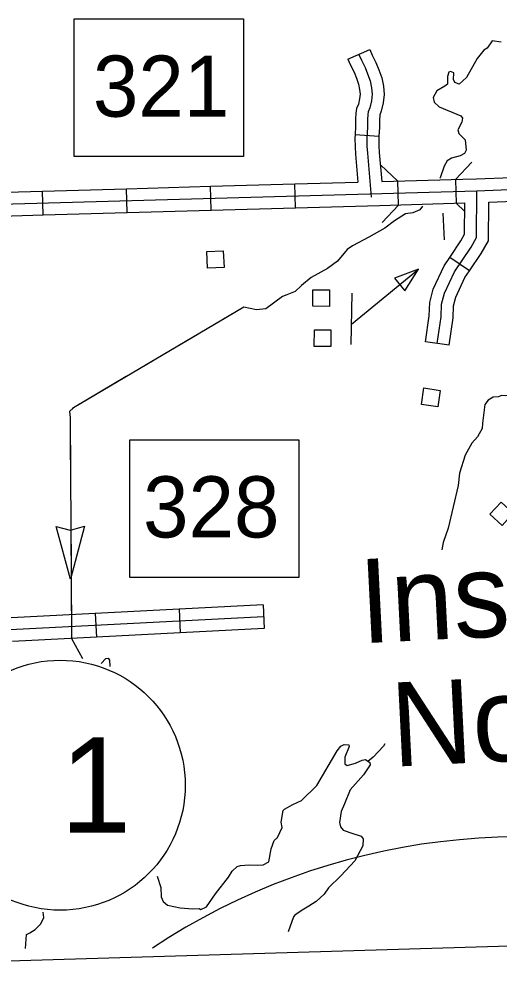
# Model space of a CAD drawing. Extents: x 1671357 to 13005564, y 567358 to 14261451.
# Drawn here: x 12758300.579 to 12758301.586, y 14259944.261 to 14259946.246 of the extents above; entities that cross this region are included whole.
import ezdxf

# ---------------------------------------------------------------- set-up
doc = ezdxf.new("R2010")
doc.units = 0
for name, color, linetype in [('32', 7, 'Continuous'), ('35', 7, 'Continuous'), ('38', 7, 'Continuous'), ('56', 7, 'Continuous'), ('63', 7, 'Continuous'), ('Default', 7, 'Continuous')]:
    doc.layers.add(name, color=color, linetype=linetype)

msp = doc.modelspace()

# ---------------------------------------------------------------- linework, layer by layer
at = {"layer": '32'}
for p, q in [((12758301.2694, 14259946.1615), (12758301.3151, 14259946.1818)), ((12758301.2842, 14259946.0033), (12758301.3341, 14259946.0002)), ((12758301.3753, 14259945.8559), (12758301.3739, 14259945.9059)), ((12758301.4968, 14259945.8589), (12758301.4954, 14259945.9089)), ((12758300.6304, 14259945.8347), (12758300.6289, 14259945.8847)), ((12758300.8066, 14259945.8397), (12758300.8051, 14259945.8897)), ((12758300.9828, 14259945.8447), (12758300.9813, 14259945.8948)), ((12758301.159, 14259945.8497), (12758301.1576, 14259945.8998)), ((12758301.5243, 14259945.7176), (12758301.4829, 14259945.7457)), ((12758301.4816, 14259945.5612), (12758301.432, 14259945.5682)), ((12758300.9151, 14259945.0077), (12758300.9177, 14259944.9577)), ((12758301.0912, 14259945.0168), (12758301.0937, 14259944.9668)), ((12758300.7391, 14259944.9987), (12758300.7417, 14259944.9487))]:
    msp.add_line(p, q, dxfattribs=at)
for points in [[(12758301.3151, 14259946.1818), (12758301.3203, 14259946.1701), (12758301.3281, 14259946.1545), (12758301.3341, 14259946.1395), (12758301.3401, 14259946.1224), (12758301.3436, 14259946.105), (12758301.345, 14259946.0877), (12758301.3434, 14259946.0703), (12758301.3391, 14259946.0522), (12758301.3362, 14259946.0449), (12758301.3359, 14259946.0431), (12758301.3354, 14259946.034), (12758301.3353, 14259946.0182), (12758301.3341, 14259946.0002)], [(12758301.2694, 14259946.1615), (12758301.275, 14259946.1488), (12758301.2824, 14259946.134), (12758301.2872, 14259946.1219), (12758301.2917, 14259946.1092), (12758301.2939, 14259946.098), (12758301.2947, 14259946.0879), (12758301.2939, 14259946.0784), (12758301.2912, 14259946.0674), (12758301.2874, 14259946.0578), (12758301.2861, 14259946.0481), (12758301.2853, 14259946.0357), (12758301.2852, 14259946.02), (12758301.2842, 14259946.0033)], [(12758301.2922, 14259946.1716), (12758301.2977, 14259946.1594), (12758301.3052, 14259946.1443), (12758301.3107, 14259946.1307), (12758301.3159, 14259946.1158), (12758301.3187, 14259946.1015), (12758301.3199, 14259946.0878), (12758301.3187, 14259946.0744), (12758301.3152, 14259946.0598), (12758301.3118, 14259946.0513), (12758301.311, 14259946.0456), (12758301.3104, 14259946.0349), (12758301.3102, 14259946.0191), (12758301.3087, 14259945.9953), (12758301.3093, 14259945.9789), (12758301.3102, 14259945.9641), (12758301.318, 14259945.8723)], [(12758300.2528, 14259946.014), (12758300.2662, 14259945.8494), (12758301.54, 14259945.8856), (12758301.8633, 14259945.8984), (12758301.8808, 14259945.9032), (12758301.8891, 14259945.9062), (12758301.8966, 14259945.9179), (12758301.9791, 14259946.0887), (12758301.9968, 14259946.1059), (12758302.0098, 14259946.1131), (12758302.0326, 14259946.1185), (12758302.0747, 14259946.1192), (12758302.3774, 14259946.1157), (12758302.3954, 14259946.1155), (12758302.4022, 14259946.1138), (12758302.4147, 14259946.0952)], [(12758301.2842, 14259946.0033), (12758301.2837, 14259945.9956), (12758301.2843, 14259945.9777), (12758301.2852, 14259945.9624), (12758301.2902, 14259945.9036)], [(12758301.3341, 14259946.0002), (12758301.3338, 14259945.9949), (12758301.3343, 14259945.98), (12758301.3351, 14259945.9659), (12758301.3404, 14259945.905)], [(12758301.1576, 14259945.8998), (12758301.2902, 14259945.9036)], [(12758301.3404, 14259945.905), (12758301.51, 14259945.9098)], [(12758301.51, 14259945.9098), (12758301.5391, 14259945.9106), (12758301.6858, 14259945.9164)], [(12758300.4527, 14259945.8797), (12758300.6289, 14259945.8847)], [(12758300.6289, 14259945.8847), (12758300.8051, 14259945.8897)], [(12758300.8051, 14259945.8897), (12758300.9813, 14259945.8948)], [(12758300.9813, 14259945.8948), (12758301.1576, 14259945.8998)], [(12758301.4568, 14259945.5647), (12758301.4647, 14259945.621), (12758301.4659, 14259945.6475), (12758301.4716, 14259945.6709), (12758301.4928, 14259945.7157), (12758301.5276, 14259945.7671), (12758301.5391, 14259945.7874), (12758301.54, 14259945.8856)], [(12758301.5243, 14259945.7176), (12758301.5489, 14259945.7539), (12758301.5641, 14259945.7807), (12758301.5648, 14259945.8615)], [(12758301.5648, 14259945.8615), (12758301.6878, 14259945.8664)], [(12758300.8066, 14259945.8397), (12758300.9828, 14259945.8447)], [(12758300.9828, 14259945.8447), (12758301.159, 14259945.8497)], [(12758301.159, 14259945.8497), (12758301.3352, 14259945.8547)], [(12758301.3352, 14259945.8547), (12758301.5147, 14259945.8598)], [(12758301.4829, 14259945.7457), (12758301.5064, 14259945.7803), (12758301.5141, 14259945.7941), (12758301.5147, 14259945.8598)], [(12758300.4541, 14259945.8297), (12758300.6304, 14259945.8347)], [(12758300.6304, 14259945.8347), (12758300.8066, 14259945.8397)], [(12758301.432, 14259945.5682), (12758301.4398, 14259945.6233), (12758301.441, 14259945.6511), (12758301.4479, 14259945.6793), (12758301.4709, 14259945.7281), (12758301.4829, 14259945.7457)], [(12758301.4816, 14259945.5612), (12758301.4897, 14259945.6187), (12758301.4908, 14259945.644), (12758301.4954, 14259945.6625), (12758301.5146, 14259945.7032), (12758301.5243, 14259945.7176)], [(12758300.9151, 14259945.0077), (12758300.7391, 14259944.9987)], [(12758301.0912, 14259945.0168), (12758300.9151, 14259945.0077)], [(12758301.0925, 14259944.9918), (12758300.2328, 14259944.9477), (12758300.2068, 14259944.9463), (12758300.181, 14259944.9391), (12758300.1614, 14259944.9302), (12758300.1497, 14259944.9217), (12758300.1315, 14259944.9025)], [(12758300.7391, 14259944.9987), (12758300.563, 14259944.9897)], [(12758300.7417, 14259944.9487), (12758300.5656, 14259944.9397)], [(12758300.9177, 14259944.9577), (12758300.7417, 14259944.9487)], [(12758301.0937, 14259944.9668), (12758300.9177, 14259944.9577)]]:
    msp.add_lwpolyline(points, dxfattribs=at)
at = {"layer": '35'}
for p, q in [((12758300.6876, 14259945.0707), (12758300.6572, 14259945.1811)), ((12758300.6572, 14259945.1811), (12758300.6868, 14259945.1734)), ((12758300.6872, 14259945.1734), (12758300.7166, 14259945.1815)), ((12758300.7166, 14259945.1815), (12758300.6876, 14259945.0707))]:
    msp.add_line(p, q, dxfattribs=at)
for points in [[(12758301.5905, 14259946.1975), (12758301.572, 14259946.2003), (12758301.5613, 14259946.1848), (12758301.5545, 14259946.1802)], [(12758301.5545, 14259946.1802), (12758301.5402, 14259946.1628), (12758301.5181, 14259946.1233), (12758301.5024, 14259946.1092), (12758301.4932, 14259946.1125), (12758301.4906, 14259946.1188), (12758301.4914, 14259946.1329), (12758301.4842, 14259946.1359), (12758301.4813, 14259946.1345), (12758301.478, 14259946.1253), (12758301.478, 14259946.1092), (12758301.4728, 14259946.105), (12758301.4556, 14259946.0952), (12758301.4481, 14259946.0811), (12758301.4499, 14259946.0711), (12758301.461, 14259946.0619), (12758301.5062, 14259946.0424), (12758301.5098, 14259946.0375), (12758301.5081, 14259946.0294), (12758301.5001, 14259946.0136), (12758301.5021, 14259946.0057), (12758301.5151, 14259945.9921), (12758301.5173, 14259945.9704), (12758301.5136, 14259945.9636), (12758301.5044, 14259945.9588), (12758301.4866, 14259945.9541), (12758301.4772, 14259945.9483), (12758301.471, 14259945.9373)], [(12758301.471, 14259945.9373), (12758301.463, 14259945.9128), (12758301.4621, 14259945.912)], [(12758301.426, 14259945.8529), (12758301.4198, 14259945.8456), (12758301.4053, 14259945.8393), (12758301.3901, 14259945.837), (12758301.3673, 14259945.8223), (12758301.3469, 14259945.807), (12758301.3134, 14259945.7878), (12758301.279, 14259945.7702), (12758301.2674, 14259945.762), (12758301.2477, 14259945.7374), (12758301.2263, 14259945.7224), (12758301.1924, 14259945.7035), (12758301.1717, 14259945.6869), (12758301.1583, 14259945.6739), (12758301.1415, 14259945.6672), (12758301.132, 14259945.6634), (12758301.097, 14259945.6375), (12758301.0777, 14259945.6356), (12758301.0511, 14259945.6412)], [(12758301.982, 14259945.6645), (12758301.9654, 14259945.6434), (12758301.9512, 14259945.624), (12758301.9323, 14259945.6044), (12758301.9217, 14259945.6026), (12758301.9082, 14259945.5983), (12758301.8803, 14259945.5938), (12758301.8453, 14259945.5923), (12758301.8292, 14259945.5869), (12758301.822, 14259945.5823), (12758301.8144, 14259945.5726), (12758301.7884, 14259945.5168), (12758301.7834, 14259945.5086), (12758301.7689, 14259945.4966), (12758301.7587, 14259945.4938), (12758301.7539, 14259945.4895), (12758301.7403, 14259945.4856), (12758301.6653, 14259945.4744), (12758301.6337, 14259945.4636), (12758301.6007, 14259945.4555), (12758301.5923, 14259945.4558), (12758301.5841, 14259945.4528), (12758301.5741, 14259945.4527), (12758301.5633, 14259945.4462)], [(12758301.0511, 14259945.6412), (12758300.6938, 14259945.4299), (12758300.6851, 14259945.4225), (12758300.6866, 14259945.4095), (12758300.6897, 14259944.9458)], [(12758301.0511, 14259945.6412), (12758300.9942, 14259945.6076)], [(12758300.9563, 14259945.5851), (12758300.8425, 14259945.5178)], [(12758300.8045, 14259945.4954), (12758300.6938, 14259945.4299), (12758300.6911, 14259945.4276)], [(12758301.5633, 14259945.4462), (12758301.5564, 14259945.4369), (12758301.5517, 14259945.3975), (12758301.5509, 14259945.3864), (12758301.5412, 14259945.3692), (12758301.5291, 14259945.3556), (12758301.5155, 14259945.3306), (12758301.5031, 14259945.2928), (12758301.5002, 14259945.2669), (12758301.4793, 14259945.1772), (12758301.4689, 14259945.1476), (12758301.466, 14259945.1321)], [(12758300.6868, 14259945.3864), (12758300.6877, 14259945.2542)], [(12758300.6879, 14259945.2101), (12758300.6888, 14259945.0779)], [(12758300.6891, 14259945.0339), (12758300.6893, 14259945.0009)], [(12758300.6897, 14259944.9458), (12758300.7123, 14259944.9042)], [(12758300.7519, 14259944.8936), (12758300.7618, 14259944.9039), (12758300.7667, 14259944.9044), (12758300.7689, 14259944.9004), (12758300.7702, 14259944.8876)], [(12758300.8693, 14259944.4475), (12758300.8772, 14259944.4232), (12758300.8774, 14259944.4041), (12758300.8818, 14259944.3939), (12758300.8908, 14259944.3862), (12758300.9175, 14259944.3807), (12758300.9442, 14259944.3791), (12758300.9576, 14259944.3794), (12758300.961, 14259944.3772), (12758300.9728, 14259944.383), (12758300.9913, 14259944.4106), (12758301.0186, 14259944.4453), (12758301.0267, 14259944.4577), (12758301.0373, 14259944.4676), (12758301.0439, 14259944.4695), (12758301.0619, 14259944.4713), (12758301.0796, 14259944.4701), (12758301.0913, 14259944.4712), (12758301.1034, 14259944.4771), (12758301.1082, 14259944.5048), (12758301.1145, 14259944.5225), (12758301.1215, 14259944.5288), (12758301.1317, 14259944.5494), (12758301.1295, 14259944.5607), (12758301.1335, 14259944.5853), (12758301.1364, 14259944.5881), (12758301.154, 14259944.5976), (12758301.1717, 14259944.6064), (12758301.204, 14259944.6379), (12758301.247, 14259944.7105), (12758301.2547, 14259944.7198), (12758301.2615, 14259944.7238), (12758301.2712, 14259944.7232), (12758301.272, 14259944.7196), (12758301.2626, 14259944.6971), (12758301.2629, 14259944.6833), (12758301.2674, 14259944.6798), (12758301.2852, 14259944.6846), (12758301.2993, 14259944.6909), (12758301.3059, 14259944.6919), (12758301.3152, 14259944.6859), (12758301.3161, 14259944.6812), (12758301.3019, 14259944.6602), (12758301.2739, 14259944.6282), (12758301.2618, 14259944.5988), (12758301.2548, 14259944.5828), (12758301.2518, 14259944.5598), (12758301.2535, 14259944.5509), (12758301.2595, 14259944.5441), (12758301.2778, 14259944.5375), (12758301.2974, 14259944.5316), (12758301.301, 14259944.5254), (12758301.3003, 14259944.5113), (12758301.2836, 14259944.4794), (12758301.2546, 14259944.4477), (12758301.2289, 14259944.4225), (12758301.2195, 14259944.4093), (12758301.2024, 14259944.3945), (12758301.1875, 14259944.3845), (12758301.1731, 14259944.3762), (12758301.1582, 14259944.3652), (12758301.155, 14259944.3623), (12758301.1439, 14259944.3303)], [(12758301.3469, 14259944.7253), (12758301.3441, 14259944.7203), (12758301.3224, 14259944.6969), (12758301.3114, 14259944.6881)], [(12758300.5929, 14259944.2953), (12758300.5949, 14259944.3247), (12758300.6018, 14259944.3287), (12758300.6132, 14259944.3352), (12758300.6253, 14259944.3474), (12758300.6318, 14259944.3604), (12758300.6301, 14259944.3717)]]:
    msp.add_lwpolyline(points, dxfattribs=at)
at = {"layer": '38'}
msp.add_line((12758301.4957, 14259945.8844), (12758301.4957, 14259945.8844), dxfattribs=at)
for points in [[(12758301.5293, 14259945.9458), (12758301.495, 14259945.9094)], [(12758301.3375, 14259945.9397), (12758301.3739, 14259945.9054)], [(12758301.3754, 14259945.8553), (12758301.3411, 14259945.8188)], [(12758301.4964, 14259945.8593), (12758301.5146, 14259945.8422)]]:
    msp.add_lwpolyline(points, dxfattribs=at)
at = {"layer": '56'}
for p, q in [((12758301.4683, 14259945.8385), (12758301.4713, 14259945.7823)), ((12758301.2766, 14259945.6054), (12758301.4176, 14259945.7212)), ((12758301.2776, 14259945.6707), (12758301.2755, 14259945.5627))]:
    msp.add_line(p, q, dxfattribs=at)
for points in [[(12758300.9745, 14259945.7233), (12758300.9731, 14259945.758), (12758301.0079, 14259945.7595), (12758301.0094, 14259945.7247)], [(12758301.3673, 14259945.7019), (12758301.3889, 14259945.6756), (12758301.4176, 14259945.7212)], [(12758301.1956, 14259945.6431), (12758301.1959, 14259945.6778), (12758301.2308, 14259945.6775), (12758301.2304, 14259945.6427)], [(12758301.1987, 14259945.559), (12758301.199, 14259945.5938), (12758301.2338, 14259945.5934), (12758301.2335, 14259945.5587)], [(12758301.458, 14259945.4322), (12758301.4236, 14259945.4372), (12758301.4285, 14259945.4717), (12758301.4629, 14259945.4667)], [(12758301.567, 14259945.2069), (12758301.5906, 14259945.2324), (12758301.6162, 14259945.2087), (12758301.5926, 14259945.1832)]]:
    msp.add_lwpolyline(points, close=True, dxfattribs=at)
at = {"layer": '63'}
msp.add_arc((12758301.6325, 14259943.1312), 1.3986, 70.3026, 123.572, dxfattribs=at)
at = {"layer": 'Default'}
msp.add_line((12758310.0419, 14259944.551), (12758300.287, 14259944.2608), dxfattribs=at)
for points in [[(12758300.6954, 14259946.246), (12758301.05, 14259946.246), (12758301.05, 14259945.9571), (12758300.6954, 14259945.9571)], [(12758300.812, 14259945.3631), (12758301.1666, 14259945.3631), (12758301.1666, 14259945.0741), (12758300.812, 14259945.0741)]]:
    msp.add_lwpolyline(points, close=True, dxfattribs=at)
msp.add_circle((12758300.6658, 14259944.6382), 0.2623, dxfattribs=at)

# ---------------------------------------------------------------- texts
at = {"layer": '63'}
for s, p in [('Inset', (12758301.2976, 14259944.9358)), ('No. 4', (12758301.3642, 14259944.6769))]:
    msp.add_text(s, height=0.17628, rotation=2.8934, dxfattribs=at).set_placement(p)
at = {"layer": 'Default'}
for s, height, p in [('321', 0.12825, (12758300.7344, 14259946.0409)), ('328', 0.12825, (12758300.8396, 14259945.158)), ('1', 0.2, (12758300.6658, 14259944.5387))]:
    msp.add_text(s, height=height, dxfattribs=at).set_placement(p)

doc.saveas('drawing.dxf')
